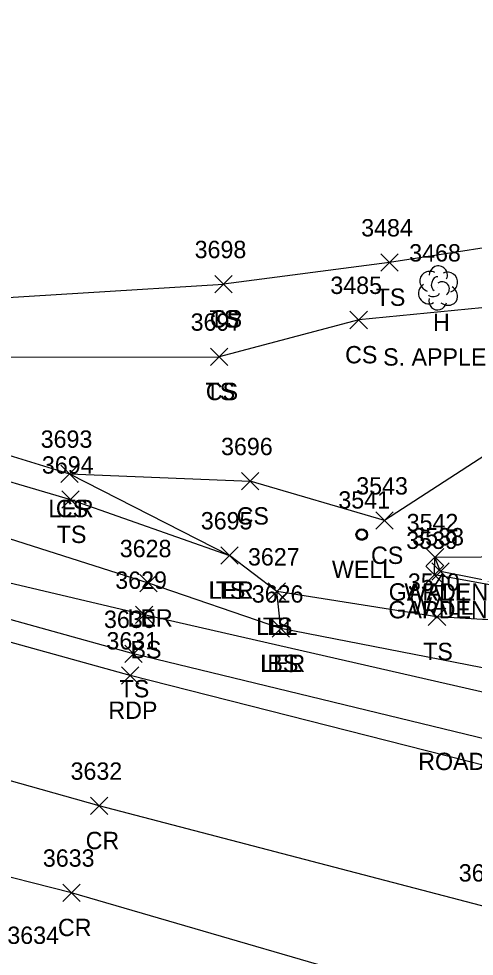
# Model space of a CAD drawing. Extents: x 1462089 to 1464015, y 730534 to 736144.
# Drawn here: x 1462748.3 to 1462800.7, y 732415.6 to 732523.6 of the extents above; entities that cross this region are included whole.
import ezdxf

# ---------------------------------------------------------------- set-up
doc = ezdxf.new("R2010")
doc.units = 0
for name, color, linetype in [('L_A', 7, 'Continuous'), ('L_C', 7, 'Continuous'), ('L_I', 7, 'Continuous'), ('L_TIC', 7, 'Continuous'), ('LAPB', 7, 'Continuous'), ('LARO', 7, 'Continuous'), ('LELB', 7, 'Continuous'), ('LTD', 7, 'Continuous'), ('LW', 7, 'Continuous'), ('P_A', 7, 'Continuous'), ('P_I', 7, 'Continuous'), ('P_TIC', 7, 'Continuous'), ('PET', 7, 'Continuous'), ('PRC', 7, 'Continuous'), ('S_C', 7, 'Continuous'), ('U_A', 7, 'Continuous'), ('U_I', 7, 'Continuous'), ('UWW', 7, 'Continuous')]:
    doc.layers.add(name, color=color, linetype=linetype)

msp = doc.modelspace()

# ---------------------------------------------------------------- linework, layer by layer
at = {"layer": 'L_TIC'}
for points in [[(1462789.98, 732494.54), (1462791.98, 732496.54)], [(1462791.98, 732494.54), (1462789.98, 732496.54)], [(1462770.85, 732492.04), (1462772.85, 732494.04)], [(1462772.85, 732492.04), (1462770.85, 732494.04)], [(1462770.85, 732492.04), (1462772.85, 732494.04)], [(1462772.85, 732492.04), (1462770.85, 732494.04)], [(1462786.43, 732487.91), (1462788.43, 732489.91)], [(1462788.43, 732487.91), (1462786.43, 732489.91)], [(1462770.38, 732483.67), (1462772.38, 732485.67)], [(1462772.38, 732483.67), (1462770.38, 732485.67)], [(1462770.38, 732483.67), (1462772.38, 732485.67)], [(1462772.38, 732483.67), (1462770.38, 732485.67)], [(1462753.12, 732470.18), (1462755.12, 732472.18)], [(1462755.12, 732470.18), (1462753.12, 732472.18)], [(1462753.12, 732470.18), (1462755.12, 732472.18)], [(1462755.12, 732470.18), (1462753.12, 732472.18)], [(1462773.94, 732469.33), (1462775.94, 732471.33)], [(1462775.94, 732469.33), (1462773.94, 732471.33)], [(1462773.94, 732469.33), (1462775.94, 732471.33)], [(1462775.94, 732469.33), (1462773.94, 732471.33)], [(1462753.25, 732467.2), (1462755.25, 732469.2)], [(1462755.25, 732467.2), (1462753.25, 732469.2)], [(1462789.41, 732464.79), (1462791.41, 732466.79)], [(1462791.41, 732464.79), (1462789.41, 732466.79)], [(1462771.55, 732460.77), (1462773.55, 732462.77)], [(1462773.55, 732460.77), (1462771.55, 732462.77)], [(1462771.55, 732460.77), (1462773.55, 732462.77)], [(1462773.55, 732460.77), (1462771.55, 732462.77)], [(1462771.55, 732460.77), (1462773.55, 732462.77)], [(1462773.55, 732460.77), (1462771.55, 732462.77)], [(1462795.22, 732460.56), (1462797.22, 732462.56)], [(1462797.22, 732460.56), (1462795.22, 732462.56)], [(1462795.22, 732460.56), (1462797.22, 732462.56)], [(1462797.22, 732460.56), (1462795.22, 732462.56)], [(1462795.18, 732458.52), (1462797.18, 732460.52)], [(1462797.18, 732458.52), (1462795.18, 732460.52)], [(1462795.87, 732458.93), (1462797.87, 732460.93)], [(1462797.87, 732458.93), (1462795.87, 732460.93)], [(1462762.23, 732457.57), (1462764.23, 732459.57)], [(1462764.23, 732457.57), (1462762.23, 732459.57)], [(1462776.99, 732456.61), (1462778.99, 732458.61)], [(1462778.99, 732456.61), (1462776.99, 732458.61)], [(1462776.99, 732456.61), (1462778.99, 732458.61)], [(1462778.99, 732456.61), (1462776.99, 732458.61)], [(1462761.72, 732453.92), (1462763.72, 732455.92)], [(1462763.72, 732453.92), (1462761.72, 732455.92)], [(1462795.45, 732453.7), (1462797.45, 732455.7)], [(1462797.45, 732453.7), (1462795.45, 732455.7)], [(1462777.48, 732452.33), (1462779.48, 732454.33)], [(1462779.48, 732452.33), (1462777.48, 732454.33)], [(1462777.48, 732452.33), (1462779.48, 732454.33)], [(1462779.48, 732452.33), (1462777.48, 732454.33)], [(1462777.48, 732452.33), (1462779.48, 732454.33)], [(1462779.48, 732452.33), (1462777.48, 732454.33)], [(1462760.49, 732449.41), (1462762.49, 732451.41)], [(1462762.49, 732449.41), (1462760.49, 732451.41)]]:
    msp.add_lwpolyline(points, dxfattribs=at)
at = {"layer": 'LAPB'}
msp.add_lwpolyline([(1462865.02, 732480.87), (1462860.49, 732471.86), (1462849.75, 732463.45), (1462837.1, 732458.56), (1462826.62, 732456.44), (1462812.24, 732456.61), (1462796.18, 732459.52), (1462796.22, 732461.56), (1462806.89, 732461.65), (1462822.28, 732460.8), (1462838.74, 732464.14), (1462849.76, 732468.75), (1462857.44, 732476.78)], dxfattribs=at)
at = {"layer": 'LARO'}
for points in [[(1462778.48, 732453.33), (1462763.23, 732458.57), (1462720.48, 732472.22), (1462676.46, 732487.15), (1462642.79, 732495.88), (1462640.52, 732506.64), (1462657.21, 732504.75), (1462675.31, 732498.01), (1462685.24, 732497.85), (1462702.41, 732489.44), (1462731.14, 732478.24), (1462754.12, 732471.18), (1462772.55, 732461.77)], [(1462778.48, 732453.33), (1462777.99, 732457.61), (1462772.55, 732461.77)]]:
    msp.add_lwpolyline(points, dxfattribs=at)
at = {"layer": 'LELB'}
for points in [[(1462929.37, 732765.22), (1462924.52, 732754.94), (1462914.85, 732728.91), (1462909.15, 732710.66), (1462894.31, 732671.59), (1462879.19, 732633.1), (1462871.41, 732624.99), (1462862.28, 732600.59), (1462856.74, 732586.46), (1462855.85, 732579.52), (1462844.58, 732549.89), (1462835, 732527.85), (1462823.24, 732513.34), (1462809.83, 732498.46), (1462790.98, 732495.54), (1462771.85, 732493.04)], [(1462962.05, 732738.86), (1462942.09, 732684.7), (1462930.35, 732649.85), (1462918.78, 732606.16), (1462910.52, 732577.08), (1462897.31, 732539.08), (1462883.37, 732494.35), (1462874.75, 732466.27), (1462864.7, 732450.44), (1462861.44, 732452.26), (1462854.05, 732449.48), (1462845.28, 732441.91), (1462832.71, 732439.48), (1462809.1, 732444.31), (1462762.72, 732454.92), (1462717.92, 732465.49), (1462675.12, 732482.37), (1462640.1, 732492.48), (1462631.96, 732496.43), (1462623.34, 732510.57), (1462622.33, 732524.87)], [(1462964.59, 732738.3), (1462945.3, 732683.44), (1462934.63, 732648.3), (1462922.94, 732604.45), (1462912.48, 732576.38), (1462900.29, 732538.09), (1462886.4, 732493.85), (1462878.64, 732463.22), (1462873.8, 732453.35), (1462865.22, 732445.19), (1462860.68, 732448.82), (1462854.34, 732445.39), (1462847.66, 732439.08), (1462833.14, 732433.31), (1462807.4, 732439.3), (1462761.49, 732450.41), (1462717.12, 732462.77), (1462672.88, 732476.46), (1462638.85, 732488.06), (1462628.32, 732495.04), (1462620.97, 732510.3), (1462619.53, 732525.27)], [(1462927.99, 732703.95), (1462913.72, 732663.31), (1462904.76, 732626.07), (1462895.22, 732616.02), (1462886.6, 732592.5), (1462880.25, 732582.3), (1462873.47, 732559.52), (1462870.27, 732539.78), (1462860.01, 732507.63), (1462849.68, 732490.92), (1462838.62, 732478.65), (1462828.6, 732476.84), (1462806.12, 732475.97), (1462790.41, 732465.79), (1462774.94, 732470.33)], [(1462938.53, 732701.15), (1462919.19, 732660.62), (1462907.45, 732626.73), (1462903.61, 732613.14), (1462893.41, 732589.66), (1462888.63, 732580.09), (1462887.4, 732563.48), (1462883.93, 732556.01), (1462884.62, 732537.6), (1462884.98, 732537.07), (1462874.27, 732495.68), (1462869.54, 732479.49), (1462861.11, 732472.14), (1462852.97, 732461.03), (1462844.11, 732457.29), (1462829.11, 732453.47), (1462814.26, 732453.65), (1462796.45, 732454.7), (1462777.99, 732457.61)], [(1462856.74, 732586.46), (1462860.95, 732575.01), (1462852.7, 732546.52), (1462847.95, 732522.58), (1462841.73, 732505.46), (1462829.4, 732491.34), (1462807.91, 732490.93), (1462787.43, 732488.91), (1462771.38, 732484.67)], [(1462902.56, 732573.66), (1462893.76, 732541.42), (1462880.65, 732494.46), (1462872.03, 732468.09), (1462861.93, 732453.56), (1462852.6, 732451.44), (1462843.02, 732445.44), (1462833.14, 732442.75), (1462809.16, 732447.34), (1462778.48, 732453.33)], [(1462638.47, 732523.02), (1462640.5, 732510.7), (1462640.52, 732506.64), (1462649.01, 732500.21), (1462662.48, 732495.14), (1462675.31, 732498.01), (1462685.76, 732493.68), (1462693.69, 732489.85), (1462700.4, 732486.38), (1462728.16, 732475.9), (1462754.25, 732468.2), (1462772.55, 732461.77)], [(1462638.47, 732523.02), (1462658.84, 732519.91), (1462689.03, 732509.97), (1462708.32, 732499.74), (1462739.49, 732491.05), (1462771.85, 732493.04)], [(1462640.5, 732510.7), (1462657.92, 732513.35), (1462687.91, 732504.52), (1462705.56, 732494.63), (1462739.13, 732484.63), (1462771.38, 732484.67)], [(1462754.12, 732471.18), (1462774.94, 732470.33)]]:
    msp.add_lwpolyline(points, dxfattribs=at)
at = {"layer": 'LTD'}
msp.add_line((1462796.55, 732492.65), (1462796.55, 732492.65), dxfattribs=at)
msp.add_line((1462796.55, 732492.65), (1462796.55, 732492.65), dxfattribs=at)
msp.add_arc((1462796.6, 732494.09), 1.05, 335.5272, 180.9563, dxfattribs=at)
for centre, major_axis, ratio, start_param, end_param in [((1462795.76, 732493.32), (1.21, -0.51), 0.895232, 1.570796, 4.712389), ((1462797.6, 732493.24), (-1.14, -0.48), 0.949671, 1.570796, 4.712389), ((1462796.35, 732493.11), (-0.208, -0.792), 0.645439, 3.141593, 6.283185), ((1462797.05, 732492.49), (-0.5, 0.667), 0.989748, 3.141593, 6.283185), ((1462795.47, 732491.95), (0.58, -1.04), 0.959034, 3.141593, 6.283185), ((1462797.55, 732491.82), (-1.09, 0.79), 0.841452, 1.570796, 4.712389), ((1462796.55, 732491.15), (0.26, 1.06), 0.942809, 1.570796, 4.712389), ((1462796.1, 732491.9), (-0.625, -0.083), 0.423636, 0, 3.141593)]:
    msp.add_ellipse(centre, major_axis=major_axis, ratio=ratio, start_param=start_param, end_param=end_param, dxfattribs=at)
at = {"layer": 'LW'}
msp.add_lwpolyline([(1462863.18, 732480.95), (1462864.44, 732480.44), (1462860.43, 732471.99), (1462849.76, 732463.59), (1462836.61, 732458.6), (1462826.7, 732456.58), (1462812.38, 732456.85), (1462796.87, 732459.93), (1462796.22, 732461.56)], dxfattribs=at)
at = {"layer": 'P_TIC'}
for points in [[(1462760.12, 732446.93), (1462762.12, 732448.93)], [(1462762.12, 732446.93), (1462760.12, 732448.93)], [(1462756.56, 732431.91), (1462758.56, 732433.91)], [(1462758.56, 732431.91), (1462756.56, 732433.91)], [(1462753.36, 732421.89), (1462755.36, 732423.89)], [(1462755.36, 732421.89), (1462753.36, 732423.89)]]:
    msp.add_lwpolyline(points, dxfattribs=at)
at = {"layer": 'PET'}
msp.add_lwpolyline([(1462878.84, 732452.24), (1462872.72, 732444.02), (1462865.19, 732437.59), (1462853.09, 732431.6), (1462850.91, 732430.96), (1462843.6, 732430.04), (1462831.16, 732430.26), (1462806.72, 732436.31), (1462761.12, 732447.93), (1462716.68, 732460.25), (1462671.34, 732472.02), (1462637.06, 732482.51), (1462580.26, 732500.42)], dxfattribs=at)
at = {"layer": 'PRC'}
for points in [[(1462860.17, 732402.54), (1462850.14, 732406.94), (1462802.36, 732421.18), (1462757.56, 732432.91), (1462714.03, 732445.15), (1462666.7, 732456.26), (1462620.19, 732470.7), (1462574.65, 732484.39)], [(1462855.98, 732390.47), (1462845.16, 732394.41), (1462798.94, 732409.88), (1462754.36, 732422.89), (1462709.64, 732434.26), (1462665.06, 732447.45), (1462615.94, 732461.58)]]:
    msp.add_lwpolyline(points, dxfattribs=at)
at = {"layer": 'UWW'}
for radius in [0.667, 0.625, 0.583, 0.542]:
    msp.add_circle((1462787.78, 732464.17), radius, dxfattribs=at)

# ---------------------------------------------------------------- texts
at = {"layer": 'L_A'}
for s, p in [('TS', (1462789.39, 732490.54)), ('TS', (1462770.26, 732488.04)), ('CS', (1462770.29, 732488.04)), ('H', (1462795.99, 732487.65)), ('CS', (1462785.87, 732483.91)), ('TS', (1462769.79, 732479.67)), ('CS', (1462769.83, 732479.67)), ('LER', (1462751.7, 732466.18)), ('CS', (1462752.56, 732466.18)), ('CS', (1462773.38, 732465.33)), ('CS', (1462773.38, 732465.33)), ('TS', (1462752.66, 732463.2)), ('CS', (1462788.85, 732460.79)), ('TS', (1462770.96, 732456.77)), ('LER', (1462770.14, 732456.77)), ('LEL', (1462770.19, 732456.77)), ('GARDEN', (1462790.89, 732456.56)), ('WALL', (1462792.71, 732456.56)), ('WALL', (1462793.36, 732454.93)), ('LER', (1462760.81, 732453.57)), ('GARDEN', (1462790.85, 732454.52)), ('LEL', (1462775.63, 732452.61)), ('TS', (1462776.4, 732452.61)), ('BS', (1462761.16, 732449.92)), ('TS', (1462794.86, 732449.7)), ('LER', (1462776.07, 732448.33)), ('LEL', (1462776.12, 732448.33)), ('BS', (1462776.92, 732448.33)), ('TS', (1462759.9, 732445.41))]:
    msp.add_text(s, height=2, dxfattribs=at).set_placement(p)
at = {"layer": 'L_C'}
msp.add_text('S. APPLE', height=2, dxfattribs=at).set_placement((1462790.25, 732483.65))
at = {"layer": 'L_I'}
for s, p in [('3484', (1462787.72, 732498.54)), ('3698', (1462768.54, 732496.04)), ('3698', (1462768.54, 732496.04)), ('3468', (1462793.25, 732495.65)), ('3485', (1462784.17, 732491.91)), ('3697', (1462768.08, 732487.67)), ('3697', (1462768.08, 732487.67)), ('3693', (1462750.81, 732474.18)), ('3693', (1462750.81, 732474.18)), ('3696', (1462771.58, 732473.33)), ('3696', (1462771.58, 732473.33)), ('3694', (1462750.95, 732471.2)), ('3543', (1462787.15, 732468.79)), ('3695', (1462769.25, 732464.77)), ('3695', (1462769.25, 732464.77)), ('3695', (1462769.25, 732464.77)), ('3542', (1462792.96, 732464.56)), ('3542', (1462792.96, 732464.56)), ('3539', (1462792.91, 732462.52)), ('3538', (1462793.61, 732462.93)), ('3628', (1462759.92, 732461.57)), ('3627', (1462774.68, 732460.61)), ('3627', (1462774.68, 732460.61)), ('3629', (1462759.4, 732457.92)), ('3540', (1462793.1, 732457.7)), ('3626', (1462775.12, 732456.33)), ('3626', (1462775.12, 732456.33)), ('3626', (1462775.12, 732456.33)), ('3630', (1462758.1, 732453.41))]:
    msp.add_text(s, height=2, dxfattribs=at).set_placement(p)
at = {"layer": 'P_A'}
for s, p in [('RDP', (1462758.61, 732442.93)), ('CR', (1462755.99, 732427.91)), ('CR', (1462752.8, 732417.89))]:
    msp.add_text(s, height=2, dxfattribs=at).set_placement(p)
at = {"layer": 'P_I'}
for s, p in [('3631', (1462758.38, 732450.93)), ('3632', (1462754.25, 732435.91)), ('3633', (1462751.06, 732425.89)), ('3620', (1462798.96, 732424.18)), ('3634', (1462746.97, 732416.99))]:
    msp.add_text(s, height=2, dxfattribs=at).set_placement(p)
at = {"layer": 'S_C'}
msp.add_text('ROAD NARROW', height=2, dxfattribs=at).set_placement((1462794.29, 732437.03))
at = {"layer": 'U_A'}
msp.add_text('WELL', height=2, dxfattribs=at).set_placement((1462784.35, 732459.17))
at = {"layer": 'U_I'}
msp.add_text('3541', height=2, dxfattribs=at).set_placement((1462785.09, 732467.17))

doc.saveas('drawing.dxf')
